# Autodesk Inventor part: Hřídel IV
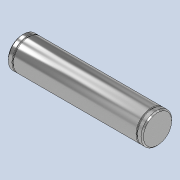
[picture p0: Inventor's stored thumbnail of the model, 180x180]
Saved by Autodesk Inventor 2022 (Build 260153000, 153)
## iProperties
Created: 2025-05
Part Number: Hřídel IV
Material: Všeobecné
Document SubType Name: Modeling
Designer: jbart
Density: 1 g/cm^3
Appearance: Broušená
Mass: 430.306 g
Surface Area: 389.769 cm^2
Volume: 430.306 cm^3
Author: jbart
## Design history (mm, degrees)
sketch "Náčrt1"
  geometry: L1 (0, 0)-(220, 0); L2 (0, 0)-(0, 25); L3 (7.85, 25)-(7.85, 23.5); L4 (7.85, 23.5)-(10.15, 23.5); L5 (10.15, 23.5)-(10.15, 25); L6 (212.15, 23.5)-(212.15, 25); L7 (212.15, 25)-(220, 25); L8 (220, 25)-(220, 0); L9 (115, 25)-(115, 0); L10 (212.15, 23.5)-(209.85, 23.5); L11 (209.85, 23.5)-(209.85, 25); L12 (10.15, 25)-(209.85, 25); L13 (0, 25)-(7.85, 25); 4 further points
  constraints: 26 end point, 5 perpendicular, 4 midpoint, 3 collinear, 3 horizontal, 3 horizontal alignment, 2 parallel, 1 point on line, 1 vertical
  dimensions: "d0" = 220 distance of L1.start L1.end; "d3" = 47 diameter of L4 L1; "d4" = 2.3 distance of L3.end L4.end; "d8" = 115 distance between parallel lines of L2 L9; "d16" = 7.85 distance of L6.end L7.end; "d17" = 50 diameter of L12 L1
revolve "Rotace1" sketch "Náčrt1" stored, may be unused: angle "d11" = 90 deg
chamfer "Zkosení1" distance "d12" = 2; stored, may be unused: second distance "d13" = 2, angle "d14" = 45 deg
node "Těleso1"
